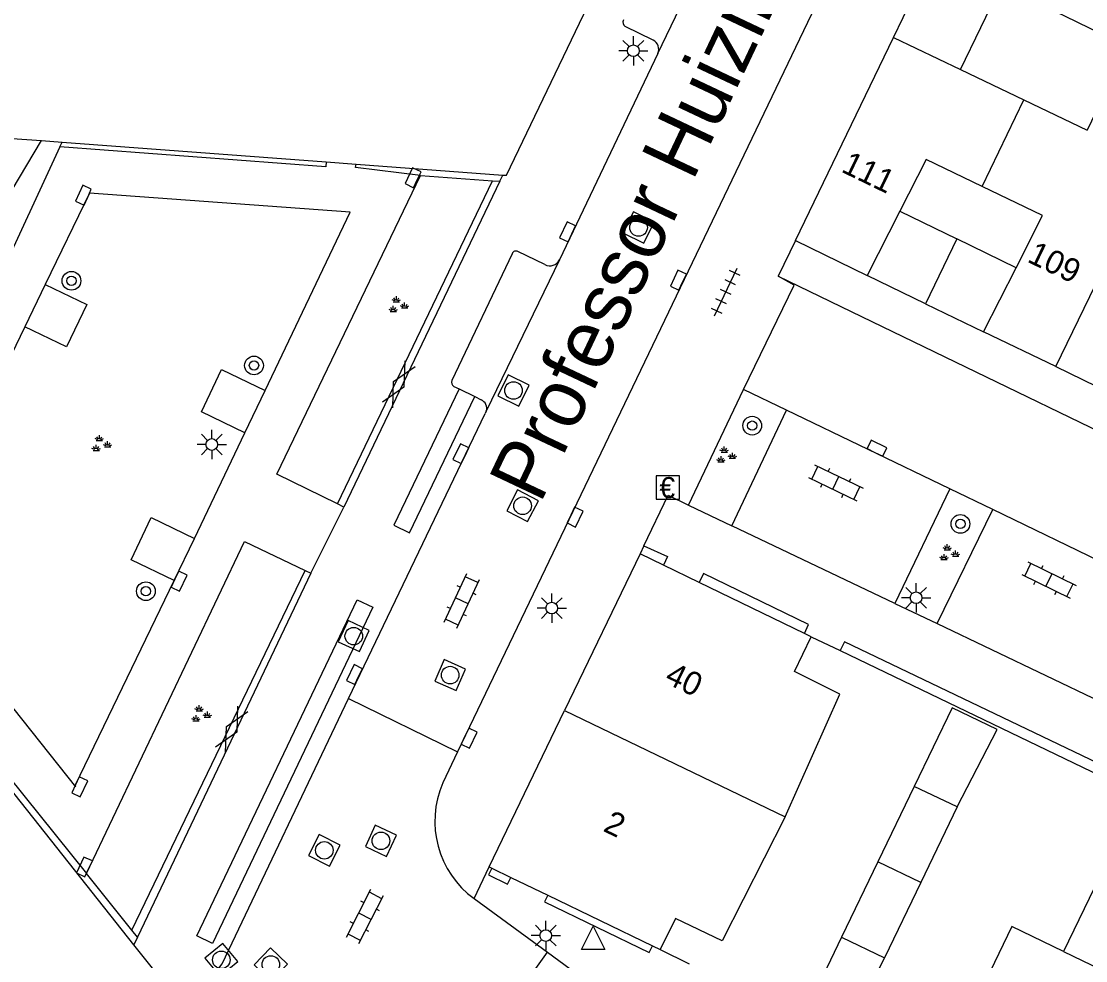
# Model space of a CAD drawing. Extents: x 132999 to 136000, y 398499 to 400501.
# Drawn here: x 134077.72 to 134123.21, y 398617.75 to 398657.89 of the extents above; entities that cross this region are included whole.
import ezdxf

# ---------------------------------------------------------------- set-up
doc = ezdxf.new("R2010")
doc.units = 0
for name, color, linetype in [('gg-afsc-hekwerk', 7, 'Continuous'), ('gg-afsc-muur', 7, 'Continuous'), ('gg-anno-huisnummerreeks BGT', 7, 'Continuous'), ('gg-anno-openbare ruimte label', 7, 'Continuous'), ('gg-bbg-bijgebouw', 7, 'Continuous'), ('gg-bbg-gedigitaliseerde bebouwing', 7, 'Continuous'), ('gg-bbg-gedigitaliseerde bijgebouw', 7, 'Continuous'), ('gg-bbg-hoofdgebouw', 7, 'Continuous'), ('gg-bbg-luifel en loopbrug', 7, 'Continuous'), ('gg-bbg-pandafbakening', 7, 'Continuous'), ('gg-bbg-tussenscheiding', 7, 'Continuous'), ('gg-knt-verharding', 7, 'Continuous'), ('gg-knt-verharding nz', 7, 'Continuous'), ('gt-grn-groengrens', 7, 'Continuous'), ('gt-grn-vlakafsluiter', 7, 'Continuous'), ('gt-symb-betaalautomaat', 7, 'Continuous'), ('gt-symb-boom', 7, 'Continuous'), ('gt-symb-gesloten verharding', 7, 'Continuous'), ('gt-symb-groenvak', 7, 'Continuous'), ('gt-symb-klinker verharding', 7, 'Continuous'), ('gt-symb-kolk', 7, 'Continuous'), ('gt-symb-lichtmast', 7, 'Continuous'), ('gt-symb-rioolschacht', 7, 'Continuous'), ('gt-symb-tegel verharding', 7, 'Continuous'), ('gt-symb-waterafsluiter', 7, 'Continuous')]:
    doc.layers.add(name, color=color, linetype=linetype)

# ---------------------------------------------------------------- blocks, each defined once
blk = doc.blocks.new('gt0-LMAST')
at = {"layer": 'gt-symb-lichtmast'}
for p, q in [((-0.005, 0.246), (-0.005, 0.621)), ((-0.182, 0.173), (-0.447, 0.438)), ((0.172, 0.173), (0.437, 0.438)), ((-0.255, -0.004), (-0.63, -0.004)), ((-0.182, -0.181), (-0.447, -0.446)), ((-0.005, -0.254), (-0.005, -0.629)), ((0.437, -0.446), (0.172, -0.181)), ((0.245, -0.004), (0.62, -0.004))]:
    blk.add_line(p, q, dxfattribs=at)
blk.add_circle((-0.005, -0.004), 0.25, dxfattribs=at)
blk = doc.blocks.new('gt0-BOOM')
at = {"layer": 'gt-symb-boom'}
for radius in [0.4, 0.2]:
    blk.add_circle((0, 0), radius, dxfattribs=at)
blk = doc.blocks.new('gt0-KOLK')
at = {"layer": 'gt-symb-kolk'}
blk.add_lwpolyline([(0, 0), (0.375, 0), (0.375, 0.4), (-0.375, 0.4), (-0.375, 0), (0, 0)], dxfattribs=at)
blk = doc.blocks.new('gt0-GRVAK')
at = {"layer": 'gt-symb-groenvak'}
for p, q in [((-0.11, 0.189), (-0.228, 0.24)), ((-0.182, 0.153), (0.088, 0.153)), ((-0.091, 0.211), (-0.156, 0.322)), ((-0.047, 0.214), (-0.047, 0.393)), ((-0.004, 0.211), (0.061, 0.322)), ((0.015, 0.189), (0.133, 0.24)), ((0.262, -0.052), (0.197, 0.059)), ((0.305, -0.049), (0.305, 0.13)), ((0.349, -0.052), (0.414, 0.059)), ((-0.245, -0.228), (-0.363, -0.177)), ((-0.318, -0.264), (-0.047, -0.264)), ((-0.226, -0.206), (-0.291, -0.095)), ((-0.183, -0.203), (-0.183, -0.024)), ((-0.139, -0.206), (-0.074, -0.095)), ((-0.12, -0.228), (-0.002, -0.177)), ((0.243, -0.074), (0.125, -0.023)), ((0.17, -0.11), (0.441, -0.11)), ((0.368, -0.074), (0.486, -0.023))]:
    blk.add_line(p, q, dxfattribs=at)
blk = doc.blocks.new('gt0-GESVH1')
at = {"layer": 'gt-symb-gesloten verharding'}
for p, q in [((-0.992, -0.261), (0.008, 0.239)), ((0.008, -0.261), (-0.992, 0.239)), ((0.008, 0.239), (1.008, -0.261)), ((1.008, 0.239), (0.008, -0.261))]:
    blk.add_line(p, q, dxfattribs=at)
blk = doc.blocks.new('gt0-BA')
at = {"layer": 'gt-symb-betaalautomaat'}
blk.add_lwpolyline([(-0.498, -0.507), (0.502, -0.507), (0.502, 0.493), (-0.498, 0.493)], close=True, dxfattribs=at)
blk.add_text('€', height=0.9, dxfattribs=at).set_placement((-0.357, -0.457))
blk = doc.blocks.new('gt0-RS')
at = {"layer": 'gt-symb-rioolschacht'}
blk.add_lwpolyline([(-0.5, -0.5), (0.5, -0.5), (0.5, 0.5), (-0.5, 0.5)], close=True, dxfattribs=at)
blk.add_circle((0, 0), 0.375, dxfattribs=at)
blk = doc.blocks.new('gt0-TEG1')
at = {"layer": 'gt-symb-tegel verharding'}
for p, q in [((-1.125, 0), (1.125, 0)), ((-0.9, -0.25), (-0.9, 0.25)), ((-0.45, -0.25), (-0.45, 0.25)), ((0, -0.25), (0, 0.25)), ((0.45, -0.25), (0.45, 0.25)), ((0.9, -0.25), (0.9, 0.25))]:
    blk.add_line(p, q, dxfattribs=at)
blk = doc.blocks.new('gt0-KL1')
at = {"layer": 'gt-symb-klinker verharding'}
for p, q in [((-1.15, 0.3), (1.15, 0.3)), ((-1, -0.3), (-1, 0.3)), ((-0.5, 0.3), (-0.5, 0.45)), ((0, -0.3), (0, 0.3)), ((0.5, 0.3), (0.5, 0.45)), ((1, -0.3), (1, 0.3)), ((-1.15, -0.3), (1.15, -0.3)), ((-0.5, -0.45), (-0.5, -0.3)), ((0.5, -0.45), (0.5, -0.3))]:
    blk.add_line(p, q, dxfattribs=at)
blk = doc.blocks.new('gt0-WAFSL')
at = {"layer": 'gt-symb-waterafsluiter'}
for p, q in [((-0.5, -0.333), (0, 0.667)), ((0, 0.667), (0.5, -0.333)), ((0.5, -0.333), (-0.5, -0.333))]:
    blk.add_line(p, q, dxfattribs=at)

msp = doc.modelspace()

# ---------------------------------------------------------------- linework, layer by layer
at = {"layer": 'gg-afsc-hekwerk'}
msp.add_line((134074.282, 398645.591), (134078.579, 398652.79), dxfattribs=at)
at = {"layer": 'gg-afsc-muur'}
for p, q in [((134111.479, 398631.598), (134112.711, 398631.004)), ((134112.711, 398631.004), (134124.216, 398625.461)), ((134105.017, 398618.227), (134106.26, 398617.628))]:
    msp.add_line(p, q, dxfattribs=at)
at = {"layer": 'gg-bbg-bijgebouw'}
for p in [(134115.266, 398649.782), (134120.231, 398647.358)]:
    msp.add_line(p, (134117.697, 398648.595), dxfattribs=at)
at = {"layer": 'gg-bbg-gedigitaliseerde bebouwing'}
for p, q in [((134117.853, 398655.823), (134120.559, 398654.527)), ((134120.559, 398654.527), (134123.265, 398653.231)), ((134110.763, 398630.112), (134111.479, 398631.598)), ((134110.357, 398623.901), (134107.675, 398618.6))]:
    msp.add_line(p, q, dxfattribs=at)
for points in [[(134117.853, 398655.823), (134119.594, 398659.429), (134122.295, 398658.124)], [(134122.295, 398658.124), (134124.997, 398656.819), (134123.265, 398653.231)], [(134110.357, 398623.901), (134112.699, 398629.144), (134110.763, 398630.112)], [(134122.256, 398618.152), (134120.053, 398619.216), (134117.453, 398613.832)]]:
    msp.add_lwpolyline(points, dxfattribs=at)
at = {"layer": 'gg-bbg-gedigitaliseerde bijgebouw'}
for p, q in [((134116.366, 398645.823), (134113.87, 398647.032)), ((134116.366, 398645.823), (134118.844, 398644.625)), ((134115.882, 398625.204), (134114.326, 398621.98)), ((134117.712, 398624.322), (134116.155, 398621.098)), ((134114.326, 398621.98), (134112.774, 398618.763)), ((134116.155, 398621.098), (134114.604, 398617.881))]:
    msp.add_line(p, q, dxfattribs=at)
for points in [[(134117.712, 398624.322), (134119.42, 398627.637), (134117.503, 398628.561), (134115.882, 398625.204)], [(134112.774, 398618.763), (134111.185, 398615.459), (134113.015, 398614.585), (134114.604, 398617.881)]]:
    msp.add_lwpolyline(points, dxfattribs=at)
at = {"layer": 'gg-bbg-hoofdgebouw'}
for p, q in [((134098.45, 398651.309), (134107.734, 398670.637)), ((134114.988, 398657.195), (134119.675, 398666.903)), ((134110.799, 398648.518), (134114.988, 398657.195)), ((134057.763, 398654.341), (134078.579, 398652.79)), ((134078.579, 398652.79), (134079.461, 398652.724)), ((134079.461, 398652.724), (134090.754, 398651.883)), ((134090.754, 398651.883), (134092.028, 398651.788)), ((134110.799, 398648.518), (134113.87, 398647.032)), ((134121.933, 398643.136), (134124.104, 398647.63)), ((134121.933, 398643.136), (134118.844, 398644.625)), ((134082.533, 398618.436), (134068.102, 398636.638)), ((134104.162, 398635.137), (134100.935, 398628.444)), ((134105.162, 398634.653), (134104.162, 398635.137)), ((134106.69, 398633.914), (134105.162, 398634.653)), ((134111.184, 398631.741), (134106.69, 398633.914)), ((134111.479, 398631.598), (134111.184, 398631.741)), ((134097.711, 398621.761), (134100.935, 398628.444)), ((134125.489, 398624.848), (134122.256, 398618.152)), ((134097.711, 398621.761), (134097.826, 398621.705)), ((134097.826, 398621.705), (134098.635, 398621.314)), ((134098.635, 398621.314), (134100.216, 398620.549)), ((134100.216, 398620.549), (134104.689, 398618.386)), ((134083.497, 398617.22), (134082.533, 398618.436)), ((134104.689, 398618.386), (134105.017, 398618.227))]:
    msp.add_line(p, q, dxfattribs=at)
for points in [[(134118.779, 398650.838), (134116.387, 398651.99), (134115.266, 398649.782)], [(134120.231, 398647.358), (134121.365, 398649.592), (134118.779, 398650.838)], [(134107.675, 398618.6), (134105.675, 398619.555), (134105.017, 398618.227)]]:
    msp.add_lwpolyline(points, dxfattribs=at)
at = {"layer": 'gg-bbg-luifel en loopbrug'}
msp.add_line((134121.933, 398643.136), (134124.528, 398641.874), dxfattribs=at)
at = {"layer": 'gg-bbg-pandafbakening'}
for p, q in [((134092.028, 398651.788), (134098.291, 398651.321)), ((134098.291, 398651.321), (134098.45, 398651.309))]:
    msp.add_line(p, q, dxfattribs=at)
at = {"layer": 'gg-bbg-tussenscheiding'}
for p, q in [((134114.988, 398657.195), (134117.853, 398655.823)), ((134118.779, 398650.838), (134120.559, 398654.527)), ((134115.266, 398649.782), (134113.87, 398647.032)), ((134117.697, 398648.595), (134116.366, 398645.823)), ((134118.844, 398644.625), (134120.231, 398647.358)), ((134100.935, 398628.444), (134110.357, 398623.901)), ((134117.712, 398624.322), (134115.882, 398625.204)), ((134116.155, 398621.098), (134114.326, 398621.98)), ((134112.774, 398618.763), (134114.604, 398617.881)), ((134122.256, 398618.152), (134129.554, 398614.629))]:
    msp.add_line(p, q, dxfattribs=at)
at = {"layer": 'gg-knt-verharding'}
for p, q in [((134114.599, 398664.689), (134096.357, 398626.673)), ((134104.72, 398657.079), (134103.52, 398657.669)), ((134104.922, 398656.519), (134100.719, 398647.693)), ((134079.366, 398652.521), (134075.782, 398644.796)), ((134098.164, 398651.056), (134098.291, 398651.321)), ((134091.225, 398637.267), (134097.851, 398651.078)), ((134098.164, 398651.056), (134091.496, 398637.133)), ((134094.772, 398651.297), (134097.851, 398651.078)), ((134097.851, 398651.078), (134098.164, 398651.056)), ((134110.799, 398648.518), (134110.068, 398647.004)), ((134098.693, 398647.958), (134096.113, 398642.546)), ((134100.093, 398647.495), (134098.943, 398648.051)), ((134078.74, 398646.641), (134077.869, 398644.841)), ((134077.869, 398644.841), (134075.69, 398640.34)), ((134096.205, 398642.291), (134096.43, 398642.181)), ((134087.272, 398640.309), (134088.135, 398642.114)), ((134096.43, 398642.181), (134093.643, 398636.36)), ((134096.43, 398642.181), (134097.095, 398641.855)), ((134097.095, 398641.855), (134097.366, 398641.722)), ((134106.235, 398637.221), (134108.582, 398642.162)), ((134110.417, 398641.282), (134108.582, 398642.162)), ((134091.708, 398628.958), (134097.548, 398641.138)), ((134097.591, 398641.227), (134097.548, 398641.138)), ((134108.082, 398636.339), (134110.417, 398641.282)), ((134117.406, 398637.914), (134110.417, 398641.282)), ((134085.116, 398635.798), (134087.272, 398640.309)), ((134117.406, 398637.914), (134115.047, 398633.017)), ((134119.239, 398637.026), (134117.406, 398637.914)), ((134091.496, 398637.133), (134091.225, 398637.267)), ((134106.235, 398637.221), (134108.082, 398636.339)), ((134090.09, 398634.307), (134091.496, 398637.133)), ((134116.858, 398632.155), (134119.239, 398637.026)), ((134126.209, 398633.651), (134119.239, 398637.026)), ((134084.253, 398633.994), (134085.116, 398635.798)), ((134104.328, 398635.485), (134104.162, 398635.137)), ((134082.446, 398619.056), (134089.848, 398634.424)), ((134090.09, 398634.307), (134082.686, 398618.757)), ((134089.848, 398634.424), (134090.09, 398634.307)), ((134115.047, 398633.017), (134116.858, 398632.155)), ((134091.708, 398628.958), (134096.357, 398626.673)), ((134096.357, 398626.673), (134095.734, 398625.348)), ((134097.073, 398620.41), (134097.711, 398621.761)), ((134082.446, 398619.056), (134080.503, 398621.477)), ((134097.073, 398620.41), (134100.202, 398618.116)), ((134082.686, 398618.757), (134082.446, 398619.056)), ((134098.005, 398615.074), (134100.202, 398618.116))]:
    msp.add_line(p, q, dxfattribs=at)
for points in [[(134090.754, 398651.883), (134090.738, 398651.674), (134079.366, 398652.521)], [(134094.772, 398651.297), (134091.996, 398651.648), (134092.028, 398651.788)], [(134091.225, 398637.267), (134088.641, 398638.546), (134094.772, 398651.297)], [(134088.135, 398642.114), (134091.775, 398649.73), (134080.629, 398650.543), (134078.74, 398646.641)], [(134108.582, 398642.162), (134110.745, 398646.622), (134110.068, 398647.004)], [(134110.068, 398647.004), (134155.388, 398625.063), (134243.841, 398582.359)], [(134074.234, 398641.984), (134070.413, 398634.012), (134080.503, 398621.477)], [(134093.643, 398636.36), (134094.31, 398636.04), (134097.095, 398641.855)], [(134074.819, 398638.54), (134072.775, 398634.318), (134080.034, 398625.185), (134080.034, 398625.267), (134084.253, 398633.994)], [(134104.328, 398635.485), (134105.357, 398637.64), (134106.235, 398637.221)], [(134080.503, 398621.477), (134087.261, 398635.67), (134089.848, 398634.424)], [(134104.328, 398635.485), (134105.339, 398635.02), (134105.162, 398634.653)], [(134111.184, 398631.741), (134111.366, 398632.116), (134106.873, 398634.293), (134106.69, 398633.914)], [(134092.066, 398633.178), (134092.735, 398632.859), (134085.896, 398618.496), (134085.227, 398618.814), (134092.066, 398633.178)], [(134124.216, 398625.461), (134124.411, 398625.866), (134112.893, 398631.381), (134112.711, 398631.004)], [(134085.413, 398616.486), (134086.299, 398617.624), (134091.708, 398628.958)], [(134097.826, 398621.705), (134097.691, 398621.427), (134098.492, 398621.018), (134098.635, 398621.314)], [(134100.216, 398620.549), (134100.079, 398620.266), (134104.552, 398618.102), (134104.689, 398618.386)], [(134100.202, 398618.116), (134102.626, 398616.338), (134105.196, 398614.413)]]:
    msp.add_lwpolyline(points, dxfattribs=at)
for centre, radius, start, end in [((134103.646, 398657.846), 0.217, 152.0601, 234.5583), ((134104.531, 398656.694), 0.429, 335.853, 63.8172), ((134098.855, 398647.906), 0.17, 58.7836, 162.0268), ((134100.305, 398647.913), 0.469, 243.1118, 331.9919), ((134096.32, 398642.476), 0.218, 161.3973, 238.28), ((134097.213, 398641.354), 0.398, 341.4136, 67.4743), ((134099.462, 398623.708), 4.073, 156.2632, 234.0801)]:
    msp.add_arc(centre, radius, start, end, dxfattribs=at)
at = {"layer": 'gg-knt-verharding nz'}
for p, q in [((134100.719, 398647.693), (134097.591, 398641.227)), ((134115.047, 398633.017), (134108.082, 398636.339)), ((134116.858, 398632.155), (134123.822, 398628.835))]:
    msp.add_line(p, q, dxfattribs=at)
msp.add_lwpolyline([(134104.922, 398656.519), (134108.116, 398663.151), (134109.854, 398666.804)], dxfattribs=at)
at = {"layer": 'gt-grn-groengrens'}
msp.add_line((134079.366, 398652.521), (134079.461, 398652.724), dxfattribs=at)
for points in [[(134078.74, 398646.641), (134080.521, 398645.783), (134079.652, 398643.981), (134077.869, 398644.841)], [(134087.272, 398640.309), (134085.414, 398641.205), (134086.271, 398643.012), (134088.135, 398642.114)], [(134084.253, 398633.994), (134082.413, 398634.88), (134083.27, 398636.687), (134085.116, 398635.798)]]:
    msp.add_lwpolyline(points, dxfattribs=at)
at = {"layer": 'gt-grn-vlakafsluiter'}
msp.add_line((134082.686, 398618.757), (134082.533, 398618.436), dxfattribs=at)

# ---------------------------------------------------------------- block references
at = {"layer": 'gt-symb-betaalautomaat'}
msp.add_blockref('gt0-BA', (134105.346, 398637.973), dxfattribs=at)
at = {"layer": 'gt-symb-boom'}
for p in [(134079.862, 398646.803), (134087.663, 398643.185), (134108.954, 398640.614), (134083.045, 398633.542)]:
    msp.add_blockref('gt0-BOOM', p, dxfattribs=at)
at = {"layer": 'gt-symb-boom', "rotation": -25.591424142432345}
msp.add_blockref('gt0-BOOM', (134117.851, 398636.414), dxfattribs=at)
at = {"layer": 'gt-symb-gesloten verharding'}
for p, rotation in [((134093.865, 398642.38), -118.35896344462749), ((134086.72, 398627.637), -118.35896344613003)]:
    msp.add_blockref('gt0-GESVH1', p, dxfattribs=dict(at, rotation=rotation))
at = {"layer": 'gt-symb-groenvak'}
for p in [(134093.796, 398645.752), (134081.102, 398639.821), (134107.805, 398639.328), (134117.338, 398635.153), (134085.368, 398628.272)]:
    msp.add_blockref('gt0-GRVAK', p, dxfattribs=at)
at = {"layer": 'gt-symb-klinker verharding'}
for p, rotation in [((134112.526, 398638.169), -25.719512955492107), ((134121.636, 398634.02), -25.84761021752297), ((134096.541, 398633.128), 65.10079947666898), ((134092.404, 398619.649), 62.92224859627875)]:
    msp.add_blockref('gt0-KL1', p, dxfattribs=dict(at, rotation=rotation))
at = {"layer": 'gt-symb-kolk'}
for p, rotation in [((134094.641, 398651.119), 64.4602671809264), ((134080.556, 398650.381), 65.66512570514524), ((134101.245, 398648.809), 64.50681862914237), ((134105.979, 398646.741), 64.28048704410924), ((134114.199, 398639.468), -25.847610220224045), ((134096.681, 398639.328), 64.28048704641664), ((134101.204, 398636.795), -115.66787516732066), ((134084.284, 398634.058), -115.79602649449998), ((134092.135, 398629.893), 64.35692916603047), ((134096.676, 398627.35), -115.59142414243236), ((134080.034, 398625.267), -115.46334506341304), ((134080.597, 398621.675), 64.79277878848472)]:
    msp.add_blockref('gt0-KOLK', p, dxfattribs=dict(at, rotation=rotation))
at = {"layer": 'gt-symb-lichtmast'}
for p in [(134103.879, 398656.636), (134085.864, 398639.812), (134115.964, 398633.264), (134100.393, 398632.822), (134100.135, 398618.832)]:
    msp.add_blockref('gt0-LMAST', p, dxfattribs=at)
at = {"layer": 'gt-symb-rioolschacht'}
for p, rotation in [((134104.097, 398649.078), 63.38370037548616), ((134098.754, 398642.117), -116.10382499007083), ((134099.141, 398637.191), -117.38497058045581), ((134091.926, 398631.622), -114.77113890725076), ((134096.047, 398629.957), 155.9734934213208), ((134090.668, 398622.471), -27.30778007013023), ((134093.087, 398622.876), -25.155372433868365), ((134086.264, 398617.791), -140.3558250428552), ((134088.382, 398617.592), 46.29643001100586)]:
    msp.add_blockref('gt0-RS', p, dxfattribs=dict(at, rotation=rotation))
at = {"layer": 'gt-symb-tegel verharding', "rotation": 64.5366549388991}
msp.add_blockref('gt0-TEG1', (134107.825, 398646.328), dxfattribs=at)
at = {"layer": 'gt-symb-waterafsluiter'}
msp.add_blockref('gt0-WAFSL', (134102.157, 398618.563), dxfattribs=at)

# ---------------------------------------------------------------- texts
at = {"layer": 'gg-anno-huisnummerreeks BGT'}
for s, rotation, p in [('111', 334.2, (134112.714, 398651.479)), ('109', 334.3, (134120.662, 398647.633)), ('40', 334.2, (134105.166, 398629.652)), ('2', 334.2, (134102.54, 398623.313))]:
    msp.add_text(s, height=1, rotation=rotation, dxfattribs=at).set_placement(p)
at = {"layer": 'gg-anno-openbare ruimte label'}
msp.add_text('Professor Huizingastraat', height=2.5, rotation=64.7, dxfattribs=at).set_placement((134099.895, 398637.238))

doc.saveas('drawing.dxf')
